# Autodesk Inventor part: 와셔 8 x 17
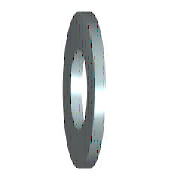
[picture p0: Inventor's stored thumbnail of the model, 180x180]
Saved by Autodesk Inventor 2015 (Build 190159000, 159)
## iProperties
IsCustomPart: 1
Created: 2012-02
Part Number: 와셔 8 x 17
Material: 강철, 연강
Description: 평면 와셔
Document SubType Name: Modeling
Standard: KS B 1326
Designer: mduedu
Standards Organization: KS
Language: ko-KR
Size Designation: 8x17
Categories: <MemberInstance><Categories><Category DisplayName="조임쇠" InternalName="e4da775c-781d-43d5-af7c-5136215cf5a6" Mnemonic="FSTN"><Category DisplayName="와셔" InternalN
Density: 7.86 g/cm^3
Mass: 2.15757 g
Surface Area: 4.70799 cm^2
Volume: 0.2745 cm^3
Appearance: 주황색
Author: mduedu
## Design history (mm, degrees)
sketch "스케치"
  geometry: C1 r 8.5 at (0, 0); C2 r 4.2 at (0, 0); 1 further point
  constraints: 2 centre point, 2 coincident
  dimensions: "d0" = 8.4 diameter of C2 (= SD1); "d1" = 17 diameter of C1 (= SD2)
extrude "본체" new body sketch "스케치" distance "d2" = 1.6 (= SD); taper "d3" = 0 deg
workaxis "Work Axis1"
workplane "Work Plane1"
body "Solid1"
other parameters: "SD1" = 8.4 [user parameter; used in 1 equation term], "SD2" = 17 [user parameter; used in 1 equation term], "SD" = 1.6 [user parameter; used in 1 equation term], "d4" = 0, "d5" = 0, "d6" = 0, "d7" = 0, "NND" = 8 [user parameter]
